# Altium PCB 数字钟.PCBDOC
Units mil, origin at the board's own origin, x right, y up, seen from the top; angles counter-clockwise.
Board outline 6000 x 4000 mil, 2 copper layers (Top Layer, Bottom Layer); 24 components, 25 nets, 156 pads, 0 vias.
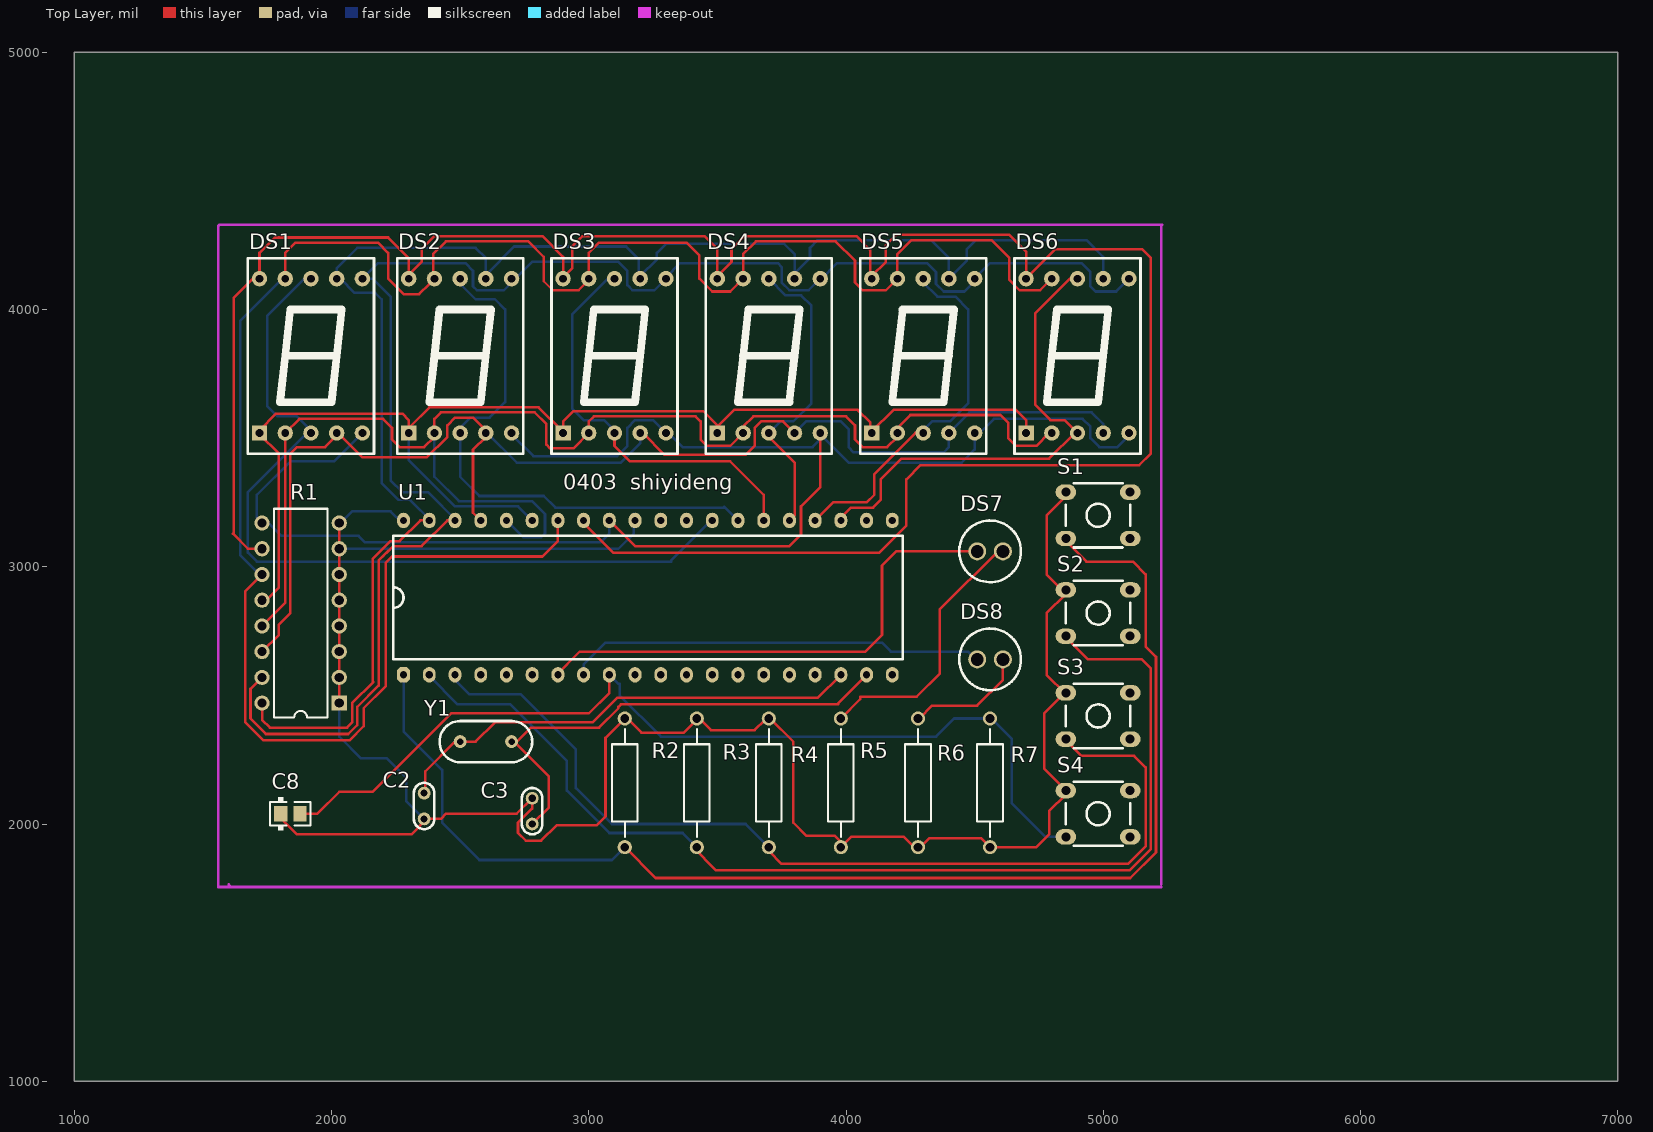
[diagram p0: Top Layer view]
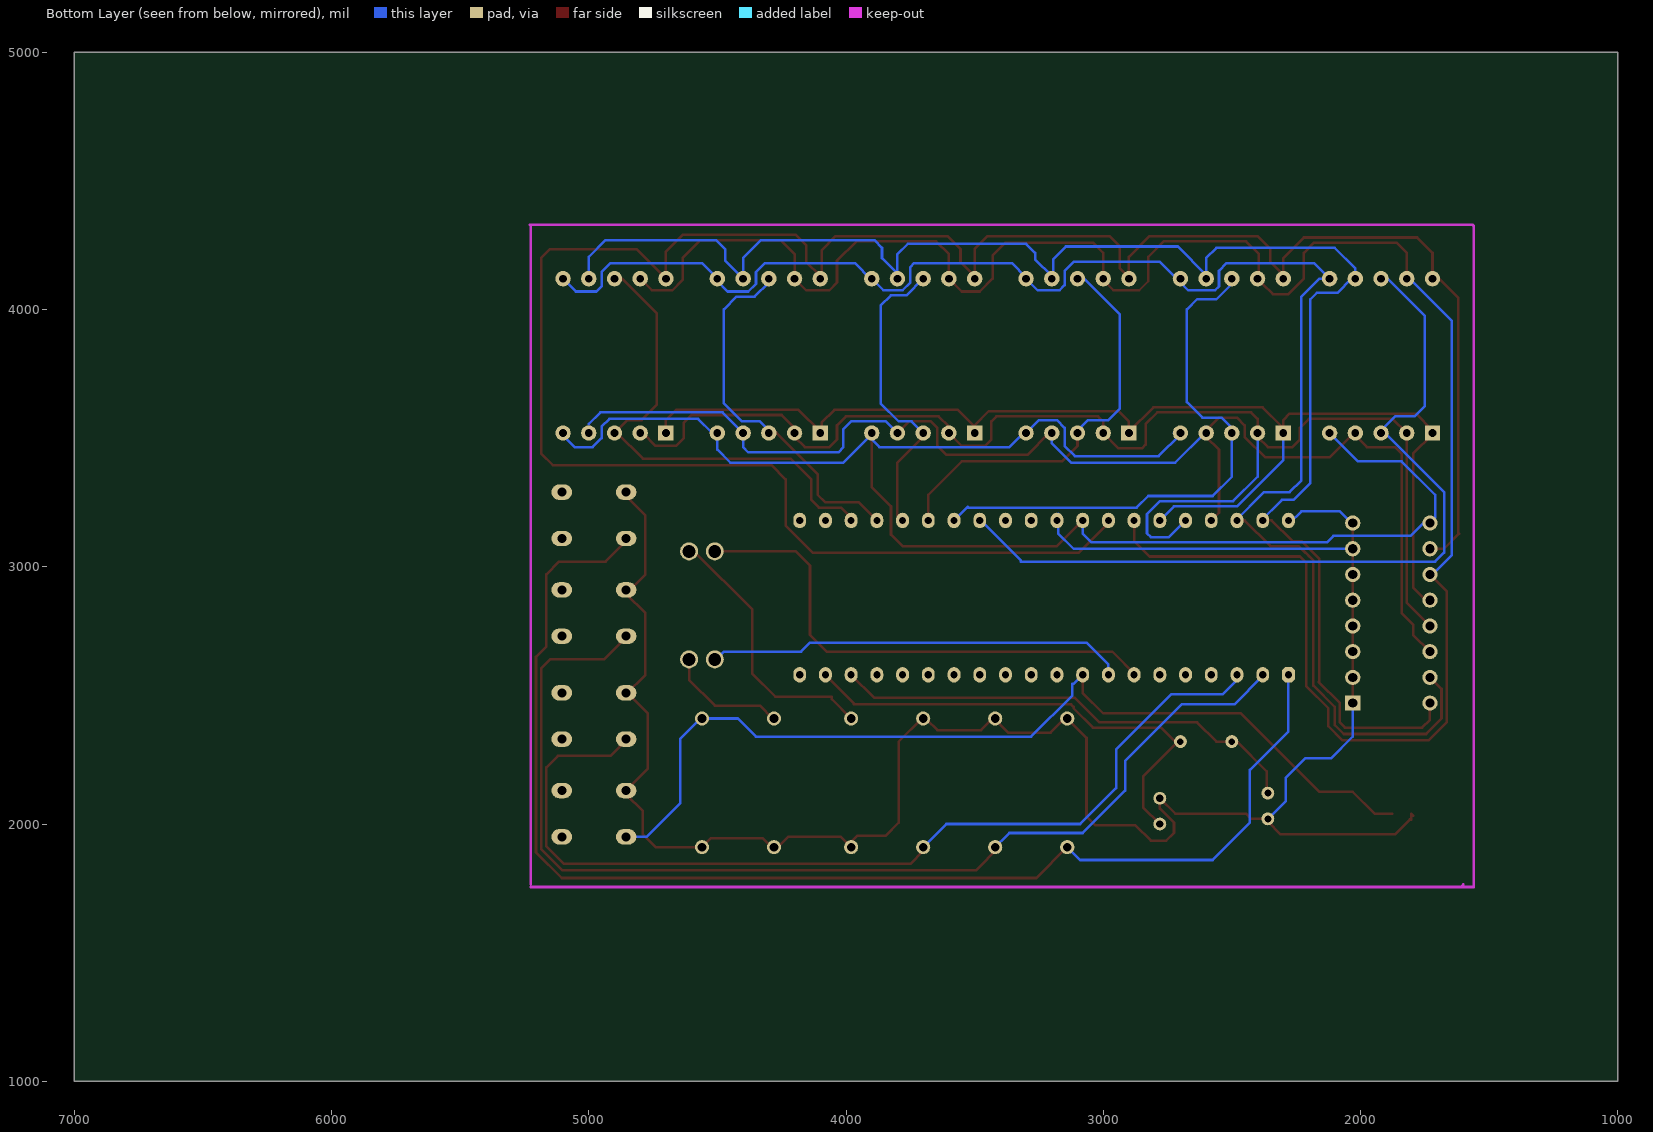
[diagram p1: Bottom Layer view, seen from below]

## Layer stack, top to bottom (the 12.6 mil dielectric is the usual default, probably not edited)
Top Layer: signal copper 1.4
Dielectric: dielectric 12.6, FR-4, Dk 4.8
Bottom Layer: signal copper 1.4

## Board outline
1000,1000 7000,1000 7000,5000 1000,5000

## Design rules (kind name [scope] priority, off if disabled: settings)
Clearance [All] p1: gap=10
ComponentClearance [All] p1: gap=10 collisioncheckmode=0
PolygonConnect [All] p1: connectstyle=Relief reliefconductorwidth=10 reliefentries=4 polygonreliefangle="90 Angle"
RoutingLayers [All] p1: top layer=Horizontal bottom layer=Vertical
RoutingVias [All] p1: holewidth=28 width=50 viastyle="Through Hole" minholewidth=28 minwidth=50 maxholewidth=28 maxwidth=50
SolderMaskExpansion [All] p1: expansion=4
TestPointUsage [All] p1: valid=0 allowmultiple=FALSE
Testpoint [All] p1: side=15 testpointundercomponent=TRUE minsize=40 maxsize=100 preferedsize=60 minholesize=0 maxholesize=40 preferedholesize=32 testpointgrid=1 style=1023 order=-539222988
Width [All] p1: maxlimit=10 minlimit=10 preferedwidth=10
16 further rules are at their usual default settings.

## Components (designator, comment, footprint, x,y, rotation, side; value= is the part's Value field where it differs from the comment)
C2 "30" CAP1.0 2360,2020 r90 top
C3 "30" CAP1.0 2780,2000 r90 top
C8 "Cap Pol3" CC2012-0805 1840,2040 r0 top
DS1 "Dpy Red-CC" SEG7 1720,4120 r0 top
DS2 "Dpy Red-CC" SEG7 2300,4120 r0 top
DS3 "Dpy Red-CC" SEG7 2900,4120 r0 top
DS4 "Dpy Red-CC" SEG7 3500,4120 r0 top
DS5 "Dpy Red-CC" SEG7 4100,4120 r0 top
DS6 "Dpy Red-CC" SEG7 4700,4120 r0 top
DS7 "LED0" LED-0 4560,3060 r0 top
DS8 "LED2" LED-0 4560,2640 r0 top
R1 "500X8" DIP-16 1880,2820 r90 top
R2 "Res Semi" AXIAL-0.5 3140,2160 r90 top
R3 "Res Semi" AXIAL-0.5 3420,2160 r90 top
R4 "Res Semi" AXIAL-0.5 3700,2160 r90 top
R5 "Res Semi" AXIAL-0.5 3980,2160 r90 top
R6 "Res Semi" AXIAL-0.5 4280,2160 r90 top
R7 "Res Semi" AXIAL-0.5 4560,2160 r90 top
S1 "SW-PB" SW6X6 4980,3200 r0 top
S2 "SW-PB" SW6X6 4980,2820 r0 top
S3 "SW-PB" SW6X6 4980,2420 r0 top
S4 "SW-PB" SW6X6 4980,2040 r0 top
U1 "AT89S51" DIP40 2280,2580 r90 top
Y1 "11.0592" CY 2700,2320 r180 top

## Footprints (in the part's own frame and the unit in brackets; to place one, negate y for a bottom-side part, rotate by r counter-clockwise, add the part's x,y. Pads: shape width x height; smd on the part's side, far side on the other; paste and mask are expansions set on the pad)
AXIAL-0.5 [mm]
  round 1.4 hole 0.85: 1(-6.35,0) 2(6.35,0)
  silkscreen extent -5.33,-1.27 5.33,1.27
CAP1.0 [mil]
  round 50 hole 28: 1(0,0) 2(100,0)
  silkscreen extent -40,-40 140,40
CC2012-0805 [mm]
  rect 1.3x1.5 smd: 1(-0.95,0) 2(0.95,0)
  silkscreen extent -2,-1.65 2,1.64
CY [mil]
  round 50 hole 25: 1(0,-0.28) 2(200,-0.28)
  silkscreen extent -80,-80 280,80
DIP40 [mil]
  oct 60x50 hole 28: 1(0,0)
  oval 60x50 hole 28: 2(0,-100) 3(0,-200) 4(0,-300) 5(0,-400) 6(0,-500) 7(0,-600) 8(0,-700) 9(0,-800) 10(0,-900) 11(0,-1000) 12(0,-1100) 13(0,-1200) 14(0,-1300) 15(0,-1400) 16(0,-1500) 17(0,-1600) 18(0,-1700) 19(0,-1800) 20(0,-1900) 21(600,-1900) 22(600,-1800) 23(600,-1700) 24(600,-1600) 25(600,-1500) 26(600,-1400) 27(600,-1300) 28(600,-1200) 29(600,-1100) 30(600,-1000) 31(600,-900) 32(600,-800) 33(600,-700) 34(600,-600) 35(600,-500) 36(600,-400) 37(600,-300) 38(600,-200) 39(600,-100) 40(600,0)
  silkscreen extent 60,-1940 540,40
DIP-16 [mm]
  rect 1.5x1.5 hole 0.9: 1(-8.89,-3.81)
  round 1.5 hole 0.9: 2(-6.35,-3.81) 3(-3.81,-3.81) 4(-1.27,-3.81) 5(1.27,-3.81) 6(3.81,-3.81) 7(6.35,-3.81) 8(8.89,-3.81) 9(8.89,3.81) 10(6.35,3.81) 11(3.81,3.81) 12(1.27,3.81) 13(-1.27,3.81) 14(-3.81,3.81) 15(-6.35,3.81) 16(-8.89,3.81)
  silkscreen extent -10.3,-2.65 10.3,2.65
LED-0 [mil]
  round 70 hole 50: 1(50,0) 2(-50,0)
  silkscreen extent -120,-120 120,120
SEG7 [mil]
  rect 60x60 hole 30: 1(0,-600)
  round 60 hole 30: 2(100,-600) 3(200,-600) 4(300,-600) 5(400,-600) 6(400,0) 7(300,0) 8(200,0) 9(100,0) 10(0,0)
  silkscreen extent -45,-680 445,80
SW6X6 [mil]
  oval 80x60 hole 35: 1(-125,90) 2(-125,-90) 3(125,90) 4(125,-90)
  silkscreen extent -125,-125 125,125

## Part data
C2 C3: library part "Cap Semi", "Capacitor (Semiconductor SIM Model)"
C8: "Polarized Capacitor (Surface Mount)"
DS1 DS2 DS3 DS4 DS5 DS6: "Common Cathhode Seven-Segment Display, Right Hand Decimal"
DS7: "Typical INFRARED GaAs LED"
DS8: "Typical RED, GREEN, YELLOW, AMBER GaAs LED"
R1: library part "Res Pack3", "Resistor Array"
R2 R3 R4 R5 R6 R7: "Semiconductor Resistor"
S1 S2 S3 S4: "Switch"
Y1: library part XTAL, "Crystal Oscillator"

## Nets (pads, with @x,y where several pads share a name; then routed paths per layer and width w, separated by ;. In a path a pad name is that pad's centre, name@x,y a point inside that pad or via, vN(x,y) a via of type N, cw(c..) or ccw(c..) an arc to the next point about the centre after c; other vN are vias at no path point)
A: DS1.7 DS2.7 DS3.7 DS4.7 DS5.7 DS6.7 R1.16 U1.39 | length 6410.4
  Top Layer w10: R1.16 1730,2405 1760,2375 2060,2375 2080,2395 2080,2470 2162.5,2552.5 ; 2160,2555 2160,3030 2230,3100 2265,3100 2345,3180 U1.39
  Bottom Layer w10: U1.39@2390,3175 2305,3260 2260,3260 2195,3325 2195,4040 2170,4065 2090,4065 2035,4120 DS1.7 2020,4160 2100,4240 2560,4240 2600,4200 DS2.7 ; DS2.7@2600,4135 2710,4245 3145,4245 3195,4195 DS3.7@3195,4135 ; DS3.7 3200,4130 3265,4195 3265,4220 3300,4255 3760,4255 3800,4215 DS4.7 ; DS4.7@3800,4140 3860,4200 3860,4240 3890,4270 4330,4270 4400,4200 DS5.7 4470,4190 4470,4235 4505,4270 4935,4270 5000,4205 DS6.7
B: DS1.6 DS2.6 DS3.6 DS4.6 DS5.6 DS6.6 R1.15 U1.38 | length 6464.1
  Top Layer w10: R1.15 1685,2525 1685,2410 1745,2350 2065,2350 2100,2385 2100,2455 2183.28,2538.28 2183.28,3025 2200,3041.72 2201.72,3041.72 2201.72,3043.43 2220,3061.72 ; 2215,3055 2240,3080 2350,3080 2450,3180 U1.38
  Bottom Layer w10: U1.38@2480,3175 U1.38 ; U1.38@2490,3175 2375,3290 2275,3290 2230,3335 2230,4050 2160,4120 DS1.6 2180,4180 2520,4180 2550,4150 2550,4090 2565,4075 2670,4075 DS2.6@2700,4105 ; DS2.6 2715,4120 2780,4185 3115,4185 3150,4150 3150,4095 3170,4075 3255,4075 DS3.6@3305,4125 ; DS3.6 3300,4125 3355,4180 3735,4180 3750,4165 3750,4105 3780,4075 3855,4075 DS4.6 ; DS4.6@3897.46,4117.46 3902.46,4117.46 3965,4180 4315,4180 4350,4145 4350,4100 4380,4070 4460,4070 4500,4110 DS5.6 4560,4180 4915,4180 4950,4145 4950,4090 4970,4070 5050,4070 DS6.6
C: DS1.4 DS2.4 DS3.4 DS4.4 DS5.4 DS6.4 R1.14 U1.37 | length 5082.2
  Top Layer w10: R1.14 1795,2735 1795,2775 1840,2820 1840,3440 1865,3465 1975,3465 2020,3510 DS1.4 2025,3520 2120,3425 2370,3425 2450,3505 2450,3550 2480,3580 2550,3580 DS2.4@2605,3525 ; U1.37 2550,3210 2550,3455 2600,3505 DS2.4 ; DS3.4 3210,3520 3295,3435 3610,3435 3645,3470 3645,3540 3670,3565 3755,3565 DS4.4
  Bottom Layer w10: DS1.4 DS1.4@2020,3530 ; DS2.4@2600,3545 DS2.4 2605,3520 2720,3405 3125,3405 3200,3480 DS3.4 ; DS4.4 3845,3565 3980,3565 4010,3535 4010,3465 4030,3445 4380,3445 4400,3465 DS5.4@4400,3530 ; DS5.4 4480,3600 4955,3600 5000,3555
D: DS1.2 DS2.2 DS3.2 DS4.2 DS5.2 DS6.2 R1.13 U1.36 | length 5430.8
  Top Layer w10: R1.13 1820,2860 DS1.2 1875,3575 2200,3575 2235,3540 2235,3495 2265,3465 2360,3465 DS2.2@2400,3505 ; DS2.2 2400,3575 2425,3600 2790,3600 2835,3555 2835,3475 2850,3460 2940,3460 DS3.2 3000,3565 3020,3585 3415,3585 3435,3565 3435,3495 3460,3470 3550,3470 DS4.2 3600,3545 3640,3585 4000,3585 4035,3550 4035,3495 4065,3465 4160,3465 DS5.2@4200,3505 ; DS5.2 4200,3540 4250,3590 4600,3590 4630,3560 4630,3500 4660,3470 4740,3470 DS6.2@4790,3520
  Bottom Layer w10: DS2.2 2400,3350 2495,3255 2780,3255 2830,3205 2830,3130 2815,3115 2745,3115 U1.36
E: DS1.1 DS2.1 DS3.1 DS4.1 DS5.1 DS6.1 R1.12 U1.35 | length 4896.2
  Top Layer w10: R1.12@1735,2860 1795,2920 1795,3440 1720,3515 1720,3530 1785,3595 2275,3595 2300,3570 DS2.1 ; DS2.1@2306.24,3546.24 2380,3620 2805,3620 DS3.1@2900,3525 ; DS3.1 2900,3565 2940,3605 3445,3605 3500,3550 ; DS4.1 3500,3545 3565,3610 4045,3610 4095,3560 DS5.1@4095,3505 ; DS5.1 4100,3525 4185,3610 4660,3610 4700,3570 4700,3510 DS6.1@4695,3505
  Bottom Layer w10: DS2.1 2300,3415 2480,3235 2725,3235 U1.35@2795,3165 ; DS3.1@2900,3515 DS3.1
F: DS1.9 DS2.9 DS3.9 DS4.9 DS5.9 DS6.9 R1.11 U1.34 | length 8142.4
  Top Layer w10: R1.11 1665,2905 1665,2395 1735,2325 2070,2325 2125,2380 2125,2450 2210,2535 2210,3015 2235,3040 2820,3040 2880,3100 U1.34 ; DS1.9 1820,4220 1860,4260 2180,4260 2220,4220 2220,4120 2280,4060 2340,4060 DS2.9@2380,4100 ; DS2.9@2395,4125 2395,4215 2445,4265 2765,4265 2825,4205 2825,4110 2860,4075 2960,4075 DS3.9@2995,4110 ; DS3.9 3000,4220 3040,4260 3380,4260 3430,4210 3430,4120 3480,4070 3550,4070 DS4.9 3600,4215 3650,4265 3960,4265 4035,4190 4035,4105 4065,4075 4155,4075 DS5.9 4200,4215 4255,4270 4565,4270 4635,4200 4635,4115 4675,4075 4755,4075 DS6.9
  Bottom Layer w10: R1.11@1735,2955 1645,3045 1645,3955 1810,4120 DS1.9
G: DS1.10 DS2.10 DS3.10 DS4.10 DS5.10 DS6.10 R1.10 U1.33 | length 9173.5
  Top Layer w10: R1.10 1675,3070 1616.31,3128.69 1619.15,3131.53 1619.15,4044.15 1695,4120 DS1.10 1720,4220 1780,4280 2220,4280 2300,4200 DS2.10 ; DS2.10@2300,4135 2350,4185 2350,4235 2400,4285 2820,4285 2900,4205 DS3.10@2900,4110 ; DS3.10@2900,4125 2935,4160 2935,4245 2975,4285 3450,4285 3500,4235 DS4.10 ; U1.33 2980,3170 3095,3055 4130,3055 4235,3160 4235,3340 4290,3395 5140,3395 5185,3440 5185,4200 5150,4235 4815,4235 DS6.10 4700,4225 4635,4290 4195,4290 4155,4250 4155,4185 4100,4130 DS5.10 ; DS4.10@3500,4130 3555,4185 3555,4235 3605,4285 4040,4285 4095,4230 DS5.10@4095,4125
NetC2_2: C2.2 U1.18 Y1.2 | length 1850.3
  Top Layer w10: C2.2@2365,2125 2365,2205 2480.28,2320.28 2560.28,2320.28 2635,2395 3015,2395 3110,2490 3890,2490 U1.18
NetC3_1: C3.1 U1.19 Y1.1 | length 1896.7
  Top Layer w10: Y1.1 2720.28,2320.28 2775,2375 3040,2375 3115,2450 3115,2455 3125,2465 3970,2465 3970,2470 U1.19 ; Y1.1@2709.72,2320.28 2845,2185 2845,2065 C3.1
NetC8_2: C8.2 R7.2 S4.2 U1.9 | length 3743.2
  Top Layer w10: C8.2 1945,2040 2030,2125 2160,2125 2465,2430 3000,2430 3080,2510 U1.9
  Bottom Layer w10: U1.9@3070,2590 3115,2545 3120,2545 3120,2500 3280,2340 4350,2340 4420,2410 R7.2 ; R7.2@4565,2410 4645,2330 4645,2080 4775,1950 S4.2
NetDS1_3: DS1.3 DS1.8 U1.28 | length 3266.7
  Bottom Layer w10: DS1.8@1910,4120 1895,4120 1750,3975 1750,3625 1790,3585 1865,3585 DS1.3@1930,3520 ; DS1.3 1905,3520 1675,3290 1675,3055 1710,3020 3320,3020 3320,3025 U1.28@3485,3190
NetDS2_3: DS2.3 DS2.8 U1.27 | length 2152
  Bottom Layer w10: DS2.3@2485,3525 2540,3580 2615,3580 2675,3640 2675,4000 2635,4040 2560,4040 2490,4110 DS2.8@2490,4115 ; DS2.3 2500,3350 2575,3275 2825,3275 2870,3230 3524.62,3230 ; 3527.31,3232.69 U1.27
NetDS3_3: DS3.3 DS3.8 U1.26 | length 1638.1
  Top Layer w10: DS3.3 3100,3470 3160,3410 3550,3410 3680,3280 U1.26@3680,3170
  Bottom Layer w10: DS3.8@3100,4110 DS3.8 3075,4120 2935,3980 2935,3615 2980,3570 3060,3570 DS3.3@3115,3515
NetDS4_3: DS4.3 DS4.8 U1.25 | length 1172.5
  Top Layer w10: DS4.3@3710,3520 DS4.3 3700,3505 3800,3405 3800,3200
  Bottom Layer w10: DS4.3 3745,3565 3795,3565 3865,3635 3865,4015 3825,4055 3765,4055 DS4.8
NetDS5_3: DS5.3 DS5.8 U1.24 | length 1424.7
  Top Layer w10: U1.24 3950,3250 4080,3250 4110,3280 4110,3360 4270,3520 DS5.3
  Bottom Layer w10: DS5.3@4300,3530 4335,3565 4405,3565 4475,3635 4475,4000 4425,4050 4355,4050 4300,4105 DS5.8
NetDS6_3: DS6.3 DS6.8 U1.23 | length 1904.2
  Top Layer w10: U1.23@3970,3180 4020,3230 4105,3230 4135,3260 4135,3340 4215,3420 4790,3420 4890,3520 DS6.3 4850,3570 4795,3570 4735,3630 4735,3985 4870,4120 DS6.8
NetDS7_1: DS7.1 R5.2 | length 1051.5
  Top Layer w10: R5.2 4055,2485 4055,2495 4275,2495 4365,2585 4365,2835 4590,3060 DS7.1
NetDS7_2: DS7.2 U1.7 | length 1999.1
  Top Layer w10: U1.7@2870,2575 2965,2670 4075,2670 4140,2735 4140,3005 4195,3060 DS7.2
NetDS8_1: DS8.1 R6.2 | length 467.1
  Top Layer w10: R6.2@4285,2410 4335,2460 4510,2460 4610,2560 DS8.1
NetDS8_2: DS8.2 U1.8 | length 1641.3
  Bottom Layer w10: U1.8 2980,2620 3065,2705 4140,2705 4175,2670 4475,2670 DS8.2@4515,2630
NetR2_1: R2.1 S1.2 U1.1 | length 5054.4
  Top Layer w10: R2.1 3260,1790 5105,1790 5205,1890 5205,2650 5165,2690 5165,2970 5115,3020 4935,3020 4855,3100 S1.2
  Bottom Layer w10: U1.1 2280,2360 2430,2210 2430,2005 2575,1860 3090,1860 R2.1
NetR3_1: R3.1 S2.2 U1.2 | length 4340.2
  Top Layer w10: R3.1@3405,1910 3495,1820 5101.72,1820 5185,1903.28 5185,2605 5150,2640 4940,2640 4855,2725 S2.2
  Bottom Layer w10: U1.2 2380,2575 2490,2465 2695,2465 2915,2245 2915,2130 3080,1965 3365,1965 R3.1@3430,1900
NetR4_1: R4.1 S3.2 U1.3 | length 3781.7
  Top Layer w10: R4.1@3700,1895 3750,1845 5095,1845 ; S3.2 4855,2325 4915,2265 5120,2265 5165,2220 5165,1913.28 5096.72,1845
  Bottom Layer w10: U1.3 2480,2560 2535,2505 2735,2505 2950,2290 2950,2140 3090,2000 3610,2000 R4.1@3705,1905
P: DS1.5 DS2.5 DS3.5 DS4.5 DS5.5 DS6.5 R1.9 U1.32 | length 6203.3
  Top Layer w10: U1.32 3180,3080 3780,3080 3825,3125 3825,3235 3900,3310 DS4.5@3900,3530
  Bottom Layer w10: R1.9@1710,3190 1710,3280 1840,3410 2010,3410 DS1.5 ; R1.9@1730,3180 1745,3180 1805,3120 2105,3120 2130,3095 3045,3095 3080,3130 U1.32 ; DS2.5@2725,3520 DS2.5 2700,3515 2785,3430 3110,3430 3150,3470 3150,3540 3180,3570 3250,3570 DS3.5 3310,3520 3365,3465 3870,3465 DS4.5@3905,3500 ; DS4.5@3900,3505 3915,3520 DS4.5 3900,3515 4010,3405 4450,3405 4500,3455 DS5.5 4520,3520 4575,3575 4920,3575 4950,3545 4950,3500 4985,3465 5055,3465 DS6.5@5100,3510
VCC: C2.1 C3.2 C8.1 R1.1 R1.2 R1.3 R1.4 R1.5 R1.6 R1.7 R1.8 R2.2 R3.2 R4.2 R5.1 R6.1 R7.1 S1.1 S2.1 S3.1 S4.1 U1.31 U1.40 | length 8669.1
  Top Layer w10: C8.1@1795,2032.4 C8.1 1802.6,2017.4 1807.6,2017.4 1865,1960 2310,1960 C2.1@2360,2010 ; R1.2@2015,2585 2025,2585 2030,2580 R1.4 ; R1.7@2020,3060 R1.7 ; R1.1 R1.2 ; R1.4@2030,2790 R1.8 ; C2.1 2425,2020 2445,2040 2720,2040 C3.2 2780,2060 2725,2005 2725,1965 2755,1935 2815,1935 2875,1995 3030,1995 3065,2030 3065,2335 R2.2 3150,2410 3205,2355 3370,2355 R3.2@3415,2400 ; R3.2 3430,2410 3475,2365 3645,2365 R4.2@3684.39,2404.39 ; R4.2 3705,2410 3795,2320 3795,2005 3845,1955 3955,1955 R5.1@3980,1930 ; R5.1 4020,1950 4225,1950 R6.1@4265,1910 ; R6.1 4290,1910 4325,1945 4525,1945 R7.1@4570,1900 ; R7.1@4545,1915 4550,1910 4740,1910 4790,1960 4790,2050 4855,2115 S4.1 4770,2215 4770,2430 4850,2510 S3.1 ; S2.1@4840,2910 4780,2970 4780,3200 4855,3275 S1.1 ; S3.1@4855,2505 4780,2580 4780,2820 4855,2895 S2.1
  Bottom Layer w10: R1.1 2030,2340 2115,2255 2215,2255 2290,2180 2290,2090 C2.1@2370,2010 ; R1.7 3115,3070 3175,3130 U1.31@3175,3205 ; R1.8@2035,3180 2045,3180 2080,3215 2230,3215 U1.40@2275,3170
pads on no net: S1.3 S1.4 S2.3 S2.4 S3.3 S3.4 S4.3 S4.4 U1.4 U1.5 U1.6 U1.10 U1.11 U1.12 U1.13 U1.14 U1.15 U1.16 U1.17 U1.20 U1.21 U1.22 U1.29 U1.30

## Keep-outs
Keep-Out Layer:
  lines w10: 1600,1765 1610,1755 ; 5190,4330 5230,4330 ; 5215,4330 1565,4330 1560,4325 1560,1755 1610,1755 ; 5225,1755 1610,1755 ; 5225,1765 5225,4325

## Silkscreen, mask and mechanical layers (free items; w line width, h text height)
Top Overlay:
  text "0403  shiyideng" at 2900,3300 h60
